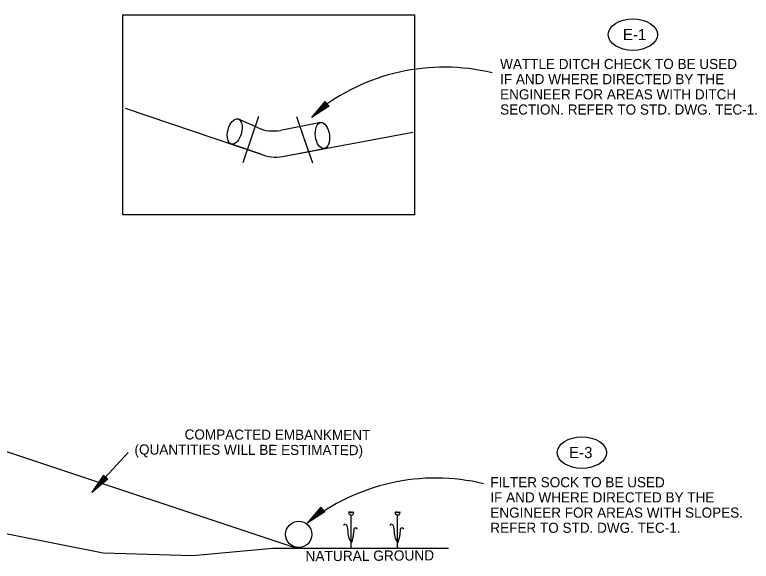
# Model space of a CAD drawing. Extents: x 1929624 to 1932072, y 596315 to 605954.
# Drawn here: x 1931120.1 to 1931556.8, y 604972.6 to 605296.7 of the extents above; entities that cross this region are included whole.
import ezdxf

# ---------------------------------------------------------------- set-up
doc = ezdxf.new("R2010")
doc.units = 0
for name, color, linetype in [('B_Concrete hidden', 7, 'Continuous'), ('B_Copy In', 7, 'Continuous'), ('Default', 7, 'Continuous')]:
    doc.layers.add(name, color=color, linetype=linetype)

msp = doc.modelspace()

# ---------------------------------------------------------------- linework, layer by layer
at = {"layer": 'B_Concrete hidden'}
for p, q in [((1931264.4212427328, 605229.6396735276), (1931252.4755796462, 605234.8885133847)), ((1931301.511237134, 605232.7222729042), (1931277.6959217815, 605228.0995167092)), ((1931265.685764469, 605214.218694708), (1931248.074842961, 605220.1785150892)), ((1931278.9604435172, 605212.6785378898), (1931303.585422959, 605217.2524762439))]:
    msp.add_line(p, q, dxfattribs=at)
msp.add_lwpolyline([(1931184.197416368, 605296.6525664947), (1931357.2046575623, 605296.6525664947), (1931357.2046575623, 605177.9506763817), (1931184.1974163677, 605177.9506763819)], close=True, dxfattribs=at)
for points in [[(1931264.7400912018, 605236.3627260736), (1931260.1806169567, 605222.9166209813), (1931255.4144801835, 605208.861058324)], [(1931287.252878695, 605236.3627260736), (1931291.8123529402, 605222.9166209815), (1931296.5784897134, 605208.8610583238)], [(1930830.2065945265, 605067.3981082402), (1931067.7495339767, 604998.4639595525), (1931172.6438580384, 604977.5975679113), (1931225.4898072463, 604975.9952981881), (1931273.100889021, 604980.3740293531), (1931377.3049588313, 604980.384810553)]]:
    msp.add_lwpolyline(points, dxfattribs=at)
msp.add_circle((1931288.4929716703, 604988.5630979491), 7.804115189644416, dxfattribs=at)
for centre, start, end in [((1931273.5304772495, 605250.1749662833), 246.07844211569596, 280.68557747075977), ((1931274.7949989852, 605234.7539874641), 246.07844211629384, 280.6855774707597), ((1931274.794998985, 605234.7539874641), 246.07844211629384, 280.6855774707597)]:
    msp.add_arc(centre, 22.465003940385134, start, end, dxfattribs=at)
for centre, major_axis, ratio in [((1931486.6206015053, 605284.8725069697), (14.604194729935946, -4.288096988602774e-12), 0.6387878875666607), ((1931250.5471976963, 605227.4383181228), (-1.9283827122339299, -7.4501950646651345), 0.5317916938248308), ((1931302.5483308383, 605224.9873746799), (1.0370929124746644, -7.734898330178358), 0.5317916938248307), ((1931456.4041617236, 605037.0619252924), (14.604194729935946, -4.288096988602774e-12), 0.6387878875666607)]:
    msp.add_ellipse(centre, major_axis=major_axis, ratio=ratio, dxfattribs=at)
at = {"layer": 'B_Copy In'}
for points in [[(1931318.3168430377, 605001.9649251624), (1931318.2988430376, 605002.0069251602), (1931318.7908430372, 605001.3049251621), (1931319.3728430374, 605002.1149251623), (1931319.7988430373, 605001.3289251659), (1931320.2308430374, 605002.114925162), (1931320.6328430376, 605001.3409251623), (1931321.0468430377, 605001.8509251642)], [(1931345.7979523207, 605001.9749565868), (1931345.7799523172, 605002.0169565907), (1931346.2719523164, 605001.3149565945), (1931346.85395232, 605002.1249565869), (1931347.279952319, 605001.3389565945), (1931347.71195232, 605002.1249565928), (1931348.1139523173, 605001.3509565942), (1931348.5279523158, 605001.8609565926)]]:
    msp.add_lwpolyline(points, dxfattribs=at)
for centre in [(1931319.6559726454, 605001.4612652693), (1931347.1370819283, 605001.4712967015)]:
    msp.add_arc(centre, 1.4559322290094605, 161.12874444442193, 15.458758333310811, dxfattribs=at)
for points in [[(1931319.4808430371, 605000.1409251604), (1931319.4028430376, 604997.0269251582), (1931319.4028430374, 604980.3349251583)], [(1931346.9619523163, 605000.1509565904), (1931346.8839523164, 604997.0369565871), (1931346.8839523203, 604980.3449565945)], [(1931319.4028430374, 604984.3069251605), (1931318.4488430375, 604986.1369251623), (1931317.7348430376, 604990.3489251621), (1931315.9048430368, 604994.5609251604), (1931315.346843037, 604994.4049251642), (1931315.1848430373, 604993.924925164)], [(1931346.8839523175, 604984.3169565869), (1931345.9299523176, 604986.1469565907), (1931345.2159523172, 604990.3589565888), (1931343.3859523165, 604994.5709565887), (1931342.8279523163, 604994.4149565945), (1931342.6659523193, 604993.9349565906)], [(1931319.4028430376, 604983.118925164), (1931319.9548430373, 604983.9889251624), (1931320.6748430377, 604986.5389251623), (1931321.3108430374, 604990.744925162), (1931321.8568430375, 604992.5089251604), (1931322.3488430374, 604992.5089251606), (1931322.8948430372, 604992.1789251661), (1931322.8948430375, 604991.7109251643)], [(1931346.8839523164, 604983.1289565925), (1931347.4359523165, 604983.9989565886), (1931348.155952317, 604986.5489565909), (1931348.7919523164, 604990.754956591), (1931349.3379523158, 604992.5189565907), (1931349.8299523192, 604992.5189565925), (1931350.3759523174, 604992.1889565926), (1931350.3759523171, 604991.7209565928)]]:
    msp.add_spline(points, degree=3, dxfattribs=at)
at = {"layer": 'Default'}
for p, q in [((1931304.073204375, 605245.2681266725), (1931296.094862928, 605235.691015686)), ((1931304.3013441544, 605245.0136001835), (1931297.651075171, 605237.0407076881)), ((1931306.330502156, 605242.7179084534), (1931297.651075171, 605237.0407076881)), ((1931304.5004306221, 605244.7782203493), (1931299.2165274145, 605238.4676529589)), ((1931306.1073157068, 605242.9483349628), (1931299.2165274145, 605238.4676529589)), ((1931304.6945637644, 605244.5669404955), (1931300.7436863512, 605239.8364916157)), ((1931305.913182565, 605243.1596148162), (1931300.7436863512, 605239.8364916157)), ((1931304.8986035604, 605244.3074606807), (1931302.2949452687, 605241.2102835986)), ((1931305.7140960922, 605243.3949946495), (1931302.2949452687, 605241.2102835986)), ((1931305.1217900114, 605244.0770341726), (1931303.8703041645, 605242.5890289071)), ((1931305.5100562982, 605243.6544744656), (1931303.8703041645, 605242.5890289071)), ((1931306.5536886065, 605242.4874819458), (1931304.073204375, 605245.2681266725)), ((1931185.6540115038, 605241.356866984), (1931265.685764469, 605214.2186947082)), ((1931306.5536886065, 605242.4874819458), (1931296.094862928, 605235.691015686)), ((1931278.9604435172, 605212.6785378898), (1931356.1770284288, 605227.0434205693)), ((1931052.390656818, 605058.5087774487), (1931287.4005935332, 604980.3848105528)), ((1931187.346251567, 605037.1862506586), (1931166.7992437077, 605014.7737498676)), ((1931172.6814164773, 605023.7105680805), (1931165.765346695, 605013.3440835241)), ((1931175.3919534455, 605021.2536286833), (1931165.765346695, 605013.3440835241)), ((1931172.9265193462, 605023.5228642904), (1931167.1448591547, 605014.8476705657)), ((1931175.1966447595, 605021.444361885), (1931167.1448591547, 605014.8476705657)), ((1931173.184481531, 605023.279210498), (1931168.6105529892, 605016.488876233)), ((1931174.9202151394, 605021.6585259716), (1931168.6105529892, 605016.488876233)), ((1931173.3613227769, 605023.0589875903), (1931169.9740797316, 605017.9887891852)), ((1931174.6935797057, 605021.8757194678), (1931169.9740797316, 605017.9887891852)), ((1931173.5929216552, 605022.8934253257), (1931171.3400881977, 605019.5145177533)), ((1931174.4411286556, 605022.0953946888), (1931171.3400881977, 605019.5145177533)), ((1931175.3919534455, 605021.2536286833), (1931172.6814164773, 605023.7105680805)), ((1931173.8213941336, 605022.6682389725), (1931172.7362310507, 605021.0555873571)), ((1931174.258776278, 605022.3395961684), (1931172.7362310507, 605021.0555873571)), ((1931301.531625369, 605004.7669438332), (1931293.5532839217, 604995.1898328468)), ((1931301.7597651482, 605004.512417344), (1931295.1094961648, 604996.5395248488)), ((1931301.9588516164, 605004.2770375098), (1931296.6749484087, 604997.9664701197)), ((1931303.5657367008, 605002.4471521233), (1931296.6749484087, 604997.9664701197)), ((1931302.1529847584, 605004.0657576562), (1931298.2021073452, 604999.3353087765)), ((1931303.371603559, 605002.6584319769), (1931298.2021073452, 604999.3353087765)), ((1931302.3570245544, 605003.8062778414), (1931299.7533662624, 605000.7091007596)), ((1931303.1725170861, 605002.89381181), (1931299.7533662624, 605000.7091007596)), ((1931302.5802110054, 605003.5758513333), (1931301.3287251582, 605002.0878460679)), ((1931302.9684772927, 605003.1532916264), (1931301.3287251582, 605002.0878460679)), ((1931304.0121096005, 605001.9862991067), (1931301.531625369, 605004.7669438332)), ((1931304.0121096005, 605001.9862991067), (1931293.5532839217, 604995.1898328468)), ((1931303.7889231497, 605002.2167256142), (1931295.1094961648, 604996.5395248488))]:
    msp.add_line(p, q, dxfattribs=at)
for centre in [(1931374.8118448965, 605143.8452908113), (1931369.7371128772, 604900.2507735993)]:
    msp.add_arc(centre, 121.71549329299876, 76.50196985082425, 128.75221985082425, dxfattribs=at)

# ---------------------------------------------------------------- texts
at = {"layer": 'B_Concrete hidden'}
for s, rotation, p in [('E-1', 359.9999999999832, (1931480.7141706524, 605281.596096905)), ('E-3', 359.9999999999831, (1931448.7925017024, 605033.7855152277))]:
    msp.add_text(s, height=6.6631110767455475, rotation=rotation, dxfattribs=at).set_placement(p)
at = {"layer": 'Default'}
for s, p in [('WATTLE DITCH CHECK TO BE USED', (1931407.8921698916, 605264.4581905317)), ('IF AND WHERE DIRECTED BY THE', (1931407.8921698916, 605255.4581905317)), ('ENGINEER FOR AREAS WITH DITCH ', (1931407.8921698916, 605246.4581905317)), ('SECTION. REFER TO STD. DWG. TEC-1.', (1931407.8921698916, 605237.4581905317)), ('FILTER SOCK TO BE USED', (1931402.0980091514, 605016.5018051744)), ('IF AND WHERE DIRECTED BY THE', (1931402.0980091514, 605007.5018051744)), ('ENGINEER FOR AREAS WITH SLOPES. ', (1931402.0980091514, 604998.5018051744)), ('REFER TO STD. DWG. TEC-1.', (1931402.0980091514, 604989.5018051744))]:
    msp.add_text(s, height=6, dxfattribs=at).set_placement(p)
for s, height, rotation, p in [('COMPACTED EMBANKMENT', 5.999999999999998, 359.8271259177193, (1931220.8192063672, 605044.8287259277)), ('(QUANTITIES WILL BE ESTIMATED)', 5.999999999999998, 359.8271259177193, (1931191.1152042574, 605035.9183087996)), ('NATURAL GROUND', 6.075, 0.38558745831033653, (1931292.5287828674, 604972.6351623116))]:
    msp.add_text(s, height=height, rotation=rotation, dxfattribs=at).set_placement(p)

doc.saveas('drawing.dxf')
